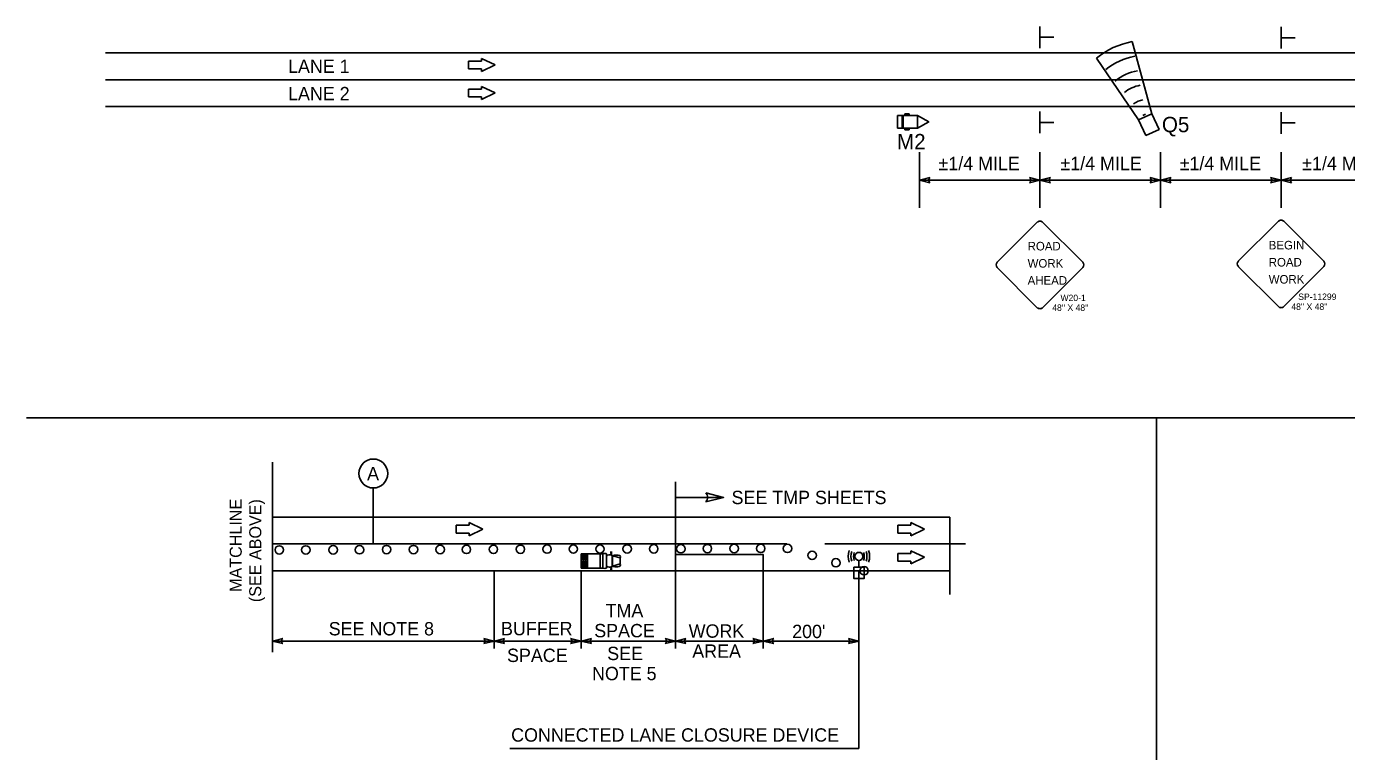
# Model space of a CAD drawing. Extents: x 1379436 to 1387057, y 792703 to 795604.
# Drawn here: x 1384807 to 1386121, y 794841 to 795563 of the extents above; entities that cross this region are included whole.
import ezdxf

# ---------------------------------------------------------------- set-up
doc = ezdxf.new("R2010")
doc.units = 0
for name, color, linetype in [('Black Area Fill Shapes', 7, 'Continuous'), ('Default', 7, 'Continuous'), ('DEV DIRECTION OF TRAFFIC FLOW ARROW CELL', 7, 'Continuous'), ('DEV LINE TERMINATOR TYPE 3 CELL', 7, 'Continuous'), ('Gray Area Fill Shapes', 7, 'Continuous'), ('Prop Mkg Skp Wht', 7, 'Continuous'), ('Prop Mkg Solid White Lane Line', 7, 'Continuous'), ('Prop Mkg Solid Yellow Edge Line', 7, 'Continuous'), ('Scratch_Level_0', 7, 'Continuous'), ('Text', 7, 'Continuous')]:
    doc.layers.add(name, color=color, linetype=linetype)

msp = doc.modelspace()

# ---------------------------------------------------------------- linework, layer by layer
at = {"layer": 'Black Area Fill Shapes'}
msp.add_lwpolyline([(1385920.9, 795454.5), (1385913.8, 795470), (1385927.1, 795476.2), (1385934.3, 795460.6)], close=True, dxfattribs=at)
for centre in [(1385058.5, 795041.9), (1385084.9, 795041.9), (1385112.1, 795042), (1385138.3, 795042.1), (1385165.3, 795042.2), (1385192.1, 795042.2), (1385218.6, 795042.3), (1385244.8, 795042.4), (1385271.6, 795042.5), (1385298.5, 795042.6), (1385325.1, 795042.7), (1385351.2, 795042.8), (1385377.7, 795042.8), (1385404.8, 795042.9), (1385431.2, 795043), (1385458.2, 795043.1), (1385484.7, 795043.2), (1385511.3, 795043.3), (1385537.7, 795043.4), (1385564.4, 795043.4), (1385588.9, 795036.5), (1385612.6, 795029.1)]:
    msp.add_circle(centre, 4.18, dxfattribs=at)
at = {"layer": 'Default'}
for p, q in [((1385695.7, 795437.9), (1385695.7, 795382.4)), ((1385815.7, 795437.9), (1385815.7, 795382.4)), ((1385935.7, 795437.9), (1385935.7, 795382.4)), ((1386055.7, 795437.9), (1386055.7, 795382.4)), ((1386985.5, 795410.1), (1385695.7, 795410.1)), ((1384806.8, 795173.4), (1387056.8, 795173.4)), ((1385931.8, 794523.6), (1385931.8, 795173.4)), ((1385452.9, 795109.8), (1385452.9, 795021.2)), ((1385152.1, 795047.9), (1385152.1, 795103.6))]:
    msp.add_line(p, q, dxfattribs=at)
msp.add_circle((1385152.1, 795118), 14.4, dxfattribs=at)
at = {"layer": 'DEV DIRECTION OF TRAFFIC FLOW ARROW CELL'}
for p, q in [((1385259.7, 795528.7), (1385246.9, 795528.7)), ((1385246.9, 795528.7), (1385246.9, 795521)), ((1385273.5, 795524.8), (1385259.7, 795531.3)), ((1385259.7, 795531.3), (1385259.7, 795528.7)), ((1385246.9, 795521), (1385259.7, 795521)), ((1385259.7, 795518.4), (1385273.5, 795524.8)), ((1385259.7, 795521), (1385259.7, 795518.4)), ((1385273.5, 795496.9), (1385259.7, 795503.4)), ((1385259.7, 795503.4), (1385259.7, 795500.7)), ((1385259.7, 795500.7), (1385246.9, 795500.7)), ((1385246.9, 795500.7), (1385246.9, 795493)), ((1385246.9, 795493), (1385259.7, 795493)), ((1385259.7, 795490.4), (1385273.5, 795496.9)), ((1385259.7, 795493), (1385259.7, 795490.4)), ((1385261.1, 795062.6), (1385247.4, 795069.1)), ((1385247.4, 795069.1), (1385247.4, 795066.5)), ((1385700.7, 795062.6), (1385687, 795069.1)), ((1385687, 795069.1), (1385687, 795066.5)), ((1385247.4, 795066.5), (1385234.6, 795066.5)), ((1385234.6, 795066.5), (1385234.6, 795058.7)), ((1385234.6, 795058.7), (1385247.4, 795058.7)), ((1385247.4, 795056.1), (1385261.1, 795062.6)), ((1385247.4, 795058.7), (1385247.4, 795056.1)), ((1385687, 795066.5), (1385674.2, 795066.5)), ((1385674.2, 795066.5), (1385674.2, 795058.7)), ((1385674.2, 795058.7), (1385687, 795058.7)), ((1385687, 795056.1), (1385700.7, 795062.6)), ((1385687, 795058.7), (1385687, 795056.1)), ((1385687, 795038.5), (1385674.2, 795038.5)), ((1385674.2, 795038.5), (1385674.2, 795030.8)), ((1385674.2, 795030.8), (1385687, 795030.8)), ((1385700.7, 795034.6), (1385687, 795041.1)), ((1385687, 795041.1), (1385687, 795038.5)), ((1385687, 795028.2), (1385700.7, 795034.6)), ((1385687, 795030.8), (1385687, 795028.2))]:
    msp.add_line(p, q, dxfattribs=at)
at = {"layer": 'DEV LINE TERMINATOR TYPE 3 CELL'}
msp.add_lwpolyline([(1385483, 795089.7), (1385500.8, 795094.2), (1385483, 795098.6)], dxfattribs=at)
msp.add_lwpolyline([(1385483, 795089.7), (1385500.8, 795094.2), (1385483, 795098.6)], dxfattribs=at)
msp.add_arc((1385479.1, 795094.2), 5.92, 311.3264, 48.6736, dxfattribs=at)
msp.add_arc((1385479.1, 795094.2), 5.92, 311.3264, 48.6736, dxfattribs=at)
at = {"layer": 'Gray Area Fill Shapes'}
msp.add_lwpolyline([(1385452.9, 795037.2), (1385540.3, 795037.2), (1385540.3, 795021.2), (1385452.9, 795021.2)], close=True, dxfattribs=at)
at = {"layer": 'Prop Mkg Skp Wht'}
for p, q in [((1384885.5, 795510.1), (1385896.2, 795510.1)), ((1385896.2, 795510.1), (1386985.5, 795510.1)), ((1385601.4, 795047.9), (1385741.4, 795047.9))]:
    msp.add_line(p, q, dxfattribs=at)
at = {"layer": 'Prop Mkg Solid White Lane Line'}
for p, q in [((1385815.7, 795563.2), (1385815.7, 795541.6)), ((1386055.7, 795562.7), (1386055.7, 795541.1)), ((1385815.7, 795552.3), (1385829.6, 795552.3)), ((1386055.7, 795551.8), (1386069.6, 795551.8)), ((1384885.5, 795483.5), (1385896.2, 795483.4)), ((1385681.3, 795476.2), (1385685.4, 795476.2)), ((1385815.7, 795478.3), (1385815.7, 795456.8)), ((1385896.2, 795483.5), (1386985.5, 795483.5)), ((1386055.7, 795477.8), (1386055.7, 795456.3)), ((1385673.7, 795474.6), (1385693.7, 795474.6)), ((1385673.7, 795461.7), (1385673.7, 795474.6)), ((1385673.7, 795474.6), (1385673.7, 795461.7)), ((1385678.4, 795461.7), (1385678.4, 795474.6)), ((1385679.5, 795461.7), (1385679.5, 795474.6)), ((1385681.3, 795475), (1385685.4, 795475)), ((1385693.7, 795461.7), (1385693.7, 795474.6)), ((1385693.7, 795474.6), (1385704.9, 795468.1)), ((1385693.7, 795461.7), (1385704.9, 795468.1)), ((1385815.7, 795467.5), (1385829.6, 795467.5)), ((1386055.7, 795467), (1386069.6, 795467)), ((1385673.7, 795461.7), (1385693.7, 795461.7)), ((1385681.3, 795461.4), (1385685.4, 795461.4)), ((1385681.3, 795460.2), (1385685.4, 795460.2)), ((1385858.2, 795323), (1385818.3, 795283.1)), ((1386098.2, 795324.1), (1386058.3, 795284.2)), ((1385051.7, 795047.9), (1385563.6, 795047.9)), ((1385358.9, 795038), (1385380.7, 795038)), ((1385358.9, 795023.9), (1385358.9, 795038)), ((1385358.9, 795038), (1385358.9, 795035.3)), ((1385358.9, 795038), (1385358.9, 795035.3)), ((1385358.9, 795038), (1385358.9, 795035.3)), ((1385358.9, 795038), (1385358.9, 795035.3)), ((1385358.9, 795035.3), (1385358.9, 795038)), ((1385358.9, 795038), (1385361.3, 795038)), ((1385361.3, 795038), (1385358.9, 795035.3)), ((1385358.9, 795033.2), (1385363.3, 795038)), ((1385365.2, 795038), (1385358.9, 795031)), ((1385358.9, 795031), (1385358.9, 795033.2)), ((1385358.9, 795031), (1385365.2, 795023.9)), ((1385358.9, 795028.9), (1385358.9, 795031)), ((1385360.9, 795031), (1385365.2, 795035.9)), ((1385365.2, 795026.2), (1385360.9, 795031)), ((1385365.2, 795033.7), (1385362.8, 795031)), ((1385362.8, 795031), (1385365.2, 795028.4)), ((1385363.3, 795038), (1385365.2, 795038)), ((1385365.2, 795023.9), (1385365.2, 795038)), ((1385365.2, 795035.9), (1385365.2, 795033.7)), ((1385377.8, 795031), (1385377.8, 795038)), ((1385377.8, 795031), (1385377.8, 795023.9)), ((1385380.7, 795031), (1385380.7, 795038)), ((1385380.7, 795031), (1385380.7, 795023.9)), ((1385384.1, 795031), (1385384.1, 795038)), ((1385384.1, 795031), (1385384.1, 795023.9)), ((1385388.6, 795038.5), (1385388.6, 795040.2)), ((1385388.9, 795036.8), (1385388.9, 795040.2)), ((1385389.1, 795036.8), (1385389.1, 795040.2)), ((1385389.7, 795031), (1385389.7, 795036.1)), ((1385389.7, 795031), (1385389.7, 795025.9)), ((1385390.2, 795036.1), (1385397.8, 795034)), ((1385390.2, 795031), (1385390.2, 795036.1)), ((1385390.2, 795031), (1385390.2, 795025.9)), ((1385397.8, 795031), (1385397.8, 795034)), ((1385397.8, 795031), (1385397.8, 795028)), ((1385051.7, 795021.2), (1385725.8, 795021.2)), ((1385363.3, 795023.9), (1385358.9, 795028.9)), ((1385358.9, 795026.6), (1385358.9, 795023.9)), ((1385361.3, 795023.9), (1385358.9, 795026.6)), ((1385358.9, 795023.9), (1385380.7, 795023.9)), ((1385358.9, 795023.9), (1385361.3, 795023.9)), ((1385365.2, 795023.9), (1385363.3, 795023.9)), ((1385365.2, 795028.4), (1385365.2, 795026.2)), ((1385388.6, 795023.5), (1385388.6, 795021.8)), ((1385388.9, 795025.2), (1385388.9, 795021.8)), ((1385389.1, 795025.2), (1385389.1, 795021.8)), ((1385390.2, 795025.9), (1385397.8, 795028))]:
    msp.add_line(p, q, dxfattribs=at)
for points in [[(1385706.1, 795407.5), (1385695.7, 795410.1), (1385706.1, 795412.7)], [(1385706.1, 795407.5), (1385695.7, 795410.1), (1385706.1, 795412.7)], [(1385805.3, 795407.5), (1385815.7, 795410.1), (1385805.3, 795412.7)], [(1385805.3, 795407.5), (1385815.7, 795410.1), (1385805.3, 795412.7)], [(1385826.1, 795407.5), (1385815.7, 795410.1), (1385826.1, 795412.7)], [(1385826.1, 795407.5), (1385815.7, 795410.1), (1385826.1, 795412.7)], [(1385925.3, 795407.5), (1385935.7, 795410.1), (1385925.3, 795412.7)], [(1385925.3, 795407.5), (1385935.7, 795410.1), (1385925.3, 795412.7)], [(1385946.1, 795407.5), (1385935.7, 795410.1), (1385946.1, 795412.7)], [(1385946.1, 795407.5), (1385935.7, 795410.1), (1385946.1, 795412.7)], [(1386045.3, 795407.5), (1386055.7, 795410.1), (1386045.3, 795412.7)], [(1386045.3, 795407.5), (1386055.7, 795410.1), (1386045.3, 795412.7)], [(1386066.1, 795407.5), (1386055.7, 795410.1), (1386066.1, 795412.7)], [(1386066.1, 795407.5), (1386055.7, 795410.1), (1386066.1, 795412.7)], [(1385773.1, 795328.3), (1385813, 795368.2)], [(1385818.3, 795368.2), (1385858.2, 795328.3)], [(1386013.1, 795329.4), (1386053, 795369.3)], [(1386058.3, 795369.3), (1386098.2, 795329.4)], [(1385813, 795283.1), (1385773.1, 795323)], [(1386053, 795284.2), (1386013.1, 795324.1)], [(1385062.1, 794948.6), (1385051.7, 794951.2), (1385062.1, 794953.8)], [(1385062.1, 794948.6), (1385051.7, 794951.2), (1385062.1, 794953.8)], [(1385262, 794948.6), (1385272.3, 794951.2), (1385262, 794953.8)], [(1385262, 794948.6), (1385272.3, 794951.2), (1385262, 794953.8)], [(1385282.7, 794948.6), (1385272.3, 794951.2), (1385282.7, 794953.8)], [(1385282.7, 794948.6), (1385272.3, 794951.2), (1385282.7, 794953.8)], [(1385348.5, 794948.6), (1385358.9, 794951.2), (1385348.5, 794953.8)], [(1385348.5, 794948.6), (1385358.9, 794951.2), (1385348.5, 794953.8)], [(1385369.3, 794948.6), (1385358.9, 794951.2), (1385369.3, 794953.8)], [(1385369.3, 794948.6), (1385358.9, 794951.2), (1385369.3, 794953.8)], [(1385442.5, 794948.6), (1385452.9, 794951.2), (1385442.5, 794953.8)], [(1385442.5, 794948.6), (1385452.9, 794951.2), (1385442.5, 794953.8)], [(1385463.3, 794948.6), (1385452.9, 794951.2), (1385463.3, 794953.8)], [(1385463.3, 794948.6), (1385452.9, 794951.2), (1385463.3, 794953.8)], [(1385529.9, 794948.6), (1385540.3, 794951.2), (1385529.9, 794953.8)], [(1385529.9, 794948.6), (1385540.3, 794951.2), (1385529.9, 794953.8)], [(1385550.7, 794948.6), (1385540.3, 794951.2), (1385550.7, 794953.8)], [(1385550.7, 794948.6), (1385540.3, 794951.2), (1385550.7, 794953.8)], [(1385625, 794948.6), (1385635.4, 794951.2), (1385625, 794953.8)], [(1385625, 794948.6), (1385635.4, 794951.2), (1385625, 794953.8)]]:
    msp.add_lwpolyline(points, dxfattribs=at)
for centre, radius in [((1385705, 795468.1), 0.114), ((1385640.6, 795021.2), 4.18)]:
    msp.add_circle(centre, radius, dxfattribs=at)
for centre, radius, start, end in [((1385682, 795475.6), 0.954, 142.0883, 217.9117), ((1385684.6, 795475.6), 0.954, 322.0883, 37.9117), ((1385682, 795460.8), 0.954, 142.0883, 217.9117), ((1385684.6, 795460.8), 0.954, 322.0883, 37.9117), ((1385708.4, 795410.1), 3.46, 131.3264, 228.6736), ((1385708.4, 795410.1), 3.46, 131.3264, 228.6736), ((1385803, 795410.1), 3.46, 311.3264, 48.6736), ((1385803, 795410.1), 3.46, 311.3264, 48.6736), ((1385828.4, 795410.1), 3.46, 131.3264, 228.6736), ((1385828.4, 795410.1), 3.46, 131.3264, 228.6736), ((1385923, 795410.1), 3.46, 311.3264, 48.6736), ((1385923, 795410.1), 3.46, 311.3264, 48.6736), ((1385948.4, 795410.1), 3.46, 131.3264, 228.6736), ((1385948.4, 795410.1), 3.46, 131.3264, 228.6736), ((1386043, 795410.1), 3.46, 311.3264, 48.6736), ((1386043, 795410.1), 3.46, 311.3264, 48.6736), ((1386068.4, 795410.1), 3.46, 131.3264, 228.6736), ((1386068.4, 795410.1), 3.46, 131.3264, 228.6736), ((1385815.7, 795365.6), 3.73, 89.9935, 135), ((1385815.7, 795365.6), 3.73, 44.987, 89.9935), ((1386055.7, 795366.6), 3.73, 89.9935, 135), ((1386055.7, 795366.6), 3.73, 44.987, 89.9935), ((1385775.8, 795325.7), 3.73, 135, 225), ((1385855.6, 795325.7), 3.73, 315, 45), ((1386015.8, 795326.7), 3.73, 135, 225), ((1386095.6, 795326.7), 3.73, 315, 45), ((1385815.7, 795285.8), 3.73, 225, 270), ((1385815.7, 795285.8), 3.73, 270, 315), ((1386055.7, 795286.8), 3.73, 225, 270), ((1386055.7, 795286.8), 3.73, 270, 315), ((1385396, 795035), 2.12, 331.8801, 28.1199), ((1385396, 795027), 2.12, 331.8801, 28.1199), ((1385064.3, 794951.2), 3.46, 131.3264, 228.6736), ((1385064.3, 794951.2), 3.46, 131.3264, 228.6736), ((1385259.7, 794951.2), 3.46, 311.3264, 48.6736), ((1385259.7, 794951.2), 3.46, 311.3264, 48.6736), ((1385285, 794951.2), 3.46, 131.3264, 228.6736), ((1385285, 794951.2), 3.46, 131.3264, 228.6736), ((1385346.2, 794951.2), 3.46, 311.3264, 48.6736), ((1385346.2, 794951.2), 3.46, 311.3264, 48.6736), ((1385371.6, 794951.2), 3.46, 131.3264, 228.6736), ((1385371.6, 794951.2), 3.46, 131.3264, 228.6736), ((1385440.3, 794951.2), 3.46, 311.3264, 48.6736), ((1385440.3, 794951.2), 3.46, 311.3264, 48.6736), ((1385465.6, 794951.2), 3.46, 131.3264, 228.6736), ((1385465.6, 794951.2), 3.46, 131.3264, 228.6736), ((1385527.7, 794951.2), 3.46, 311.3264, 48.6736), ((1385527.7, 794951.2), 3.46, 311.3264, 48.6736), ((1385553, 794951.2), 3.46, 131.3264, 228.6736), ((1385553, 794951.2), 3.46, 131.3264, 228.6736), ((1385622.7, 794951.2), 3.46, 311.3264, 48.6736), ((1385622.7, 794951.2), 3.46, 311.3264, 48.6736)]:
    msp.add_arc(centre, radius, start, end, dxfattribs=at)
for centre, major_axis, ratio, start_param, end_param in [((1385382.4, 795038), (1.67, 0), 0.269913, 0, 3.141593), ((1385386.9, 795035.7), (2.8, 0.35), 0.503092, 0, 3.141593), ((1385394, 795036), (3.82, -0.04), 0.2034, 0, 3.141593), ((1385382.4, 795023.9), (1.67, 0), 0.269913, 3.141593, 6.283185), ((1385386.9, 795026.3), (2.8, -0.35), 0.503092, 3.141593, 6.283185), ((1385394, 795025.9), (3.82, 0.04), 0.2034, 3.141593, 6.283185)]:
    msp.add_ellipse(centre, major_axis=major_axis, ratio=ratio, start_param=start_param, end_param=end_param, dxfattribs=at)
at = {"layer": 'Prop Mkg Solid Yellow Edge Line'}
for p, q in [((1384885.5, 795536.7), (1385896.2, 795536.7)), ((1385896.2, 795536.7), (1386985.5, 795536.7)), ((1385051.7, 795074.5), (1385725.8, 795074.5))]:
    msp.add_line(p, q, dxfattribs=at)
at = {"layer": 'Scratch_Level_0'}
msp.add_line((1385725.8, 795074.5), (1385725.8, 794997.4), dxfattribs=at)
at = {"layer": 'Text'}
for p, q in [((1385927.1, 795476.2), (1385907.4, 795548.1)), ((1385913.8, 795470), (1385871.9, 795531.7)), ((1385051.7, 795129.4), (1385051.7, 794940)), ((1385452.9, 795094.2), (1385500.8, 795094.2)), ((1385635.5, 795024.9), (1385635.5, 795031.5)), ((1385272.3, 795021.2), (1385272.3, 794943.7)), ((1385358.9, 795021.2), (1385358.9, 794943.7)), ((1385452.9, 795021.2), (1385452.9, 794943.7)), ((1385540.3, 795021.2), (1385540.3, 794943.7)), ((1385635.5, 795021.2), (1385635.5, 794844.3)), ((1385051.7, 794951.2), (1385272.3, 794951.2)), ((1385272.3, 794951.2), (1385358.9, 794951.2)), ((1385358.9, 794951.2), (1385453, 794951.2)), ((1385452.9, 794951.2), (1385540.3, 794951.2)), ((1385540.3, 794951.2), (1385635.5, 794951.2)), ((1385635.5, 794844.3), (1385288.1, 794844.3))]:
    msp.add_line(p, q, dxfattribs=at)
msp.add_lwpolyline([(1385630.4, 795024.9), (1385640.6, 795024.9), (1385640.6, 795013.3), (1385630.4, 795013.3)], close=True, dxfattribs=at)
msp.add_circle((1385635.5, 795035.5), 3.99, dxfattribs=at)
for centre, radius, start, end in [((1385921.9, 795469.9), 79.4, 100.4731, 129.0092), ((1385921.9, 795469.9), 64.7, 100.4731, 129.0092), ((1385921.9, 795469.9), 50, 100.4731, 129.0092), ((1385921.9, 795469.9), 35.3, 100.4731, 129.0092), ((1385921.9, 795469.9), 20.6, 100.4731, 129.0092), ((1385921.9, 795469.9), 5.93, 100.4731, 129.0092), ((1385642.5, 795035.5), 17.6, 161.0657, 198.9343), ((1385642.5, 795035.5), 15, 161.0657, 198.9343), ((1385642.5, 795035.5), 12.3, 161.0657, 198.9343), ((1385628.5, 795035.5), 12.3, 341.0657, 18.9343), ((1385628.5, 795035.5), 15, 341.0657, 18.9343), ((1385628.5, 795035.5), 17.6, 341.0657, 18.9343)]:
    msp.add_arc(centre, radius, start, end, dxfattribs=at)

# ---------------------------------------------------------------- texts
at = {"layer": 'Default'}
for s, p in [('MATCHLINE', (1385021.1, 795000.1)), ('(SEE ABOVE)', (1385040.6, 794989.9))]:
    msp.add_text(s, height=12, rotation=90, dxfattribs=at).set_placement(p)
at = {"layer": 'Prop Mkg Solid White Lane Line'}
for s, height, p in [('ROAD', 8.52, (1385803.4, 795340.1)), ('BEGIN', 8.52, (1386043.4, 795341.1)), ('WORK', 8.52, (1385803.4, 795323)), ('ROAD', 8.52, (1386043.4, 795324.1)), ('AHEAD', 8.52, (1385803.4, 795306)), ('WORK', 8.52, (1386043.4, 795307.1)), ('W20-1', 6.39, (1385836.1, 795289.7)), ('SP-11299', 6.39, (1386072.8, 795290.8)), ("48'' X 48''", 6.389, (1385827.9, 795279.9)), ("48'' X 48''", 6.389, (1386065.9, 795280.9))]:
    msp.add_text(s, height=height, dxfattribs=at).set_placement(p)
at = {"layer": 'Text'}
for s, height, p in [('LANE 1', 13.31, (1385067.2, 795516.8)), ('LANE 2', 13.31, (1385067.2, 795489.6)), ('Q5', 15.29, (1385937.1, 795457.8)), ('M2', 15.29, (1385673.4, 795440.8)), ('±1/4 MILE', 13.31, (1385714.7, 795420)), ('±1/4 MILE', 13.31, (1385836, 795420)), ('±1/4 MILE', 13.31, (1385954.7, 795420)), ('±1/4 MILE', 13.31, (1386076.7, 795420)), ('A', 13.3, (1385145.9, 795111.3)), ('SEE TMP SHEETS', 13.304, (1385508.7, 795087.5)), ('TMA', 13.3, (1385383.3, 794974.9)), ('SEE NOTE 8', 13.3, (1385107.7, 794956.8)), ('BUFFER ', 13.31, (1385279.2, 794956.9)), ('SPACE', 13.3, (1385372, 794954.9)), ('WORK ', 13.3, (1385466, 794954.5)), ("200'", 13.3, (1385569, 794954.1)), ('SPACE', 13.31, (1385285.2, 794930.3)), ('SEE ', 13.3, (1385384.9, 794932.2)), ('AREA', 13.3, (1385469.6, 794934.5)), ('NOTE 5', 13.3, (1385369.8, 794912.2)), ('CONNECTED LANE CLOSURE DEVICE', 13.31, (1385289.3, 794851))]:
    msp.add_text(s, height=height, dxfattribs=at).set_placement(p)

doc.saveas('drawing.dxf')
